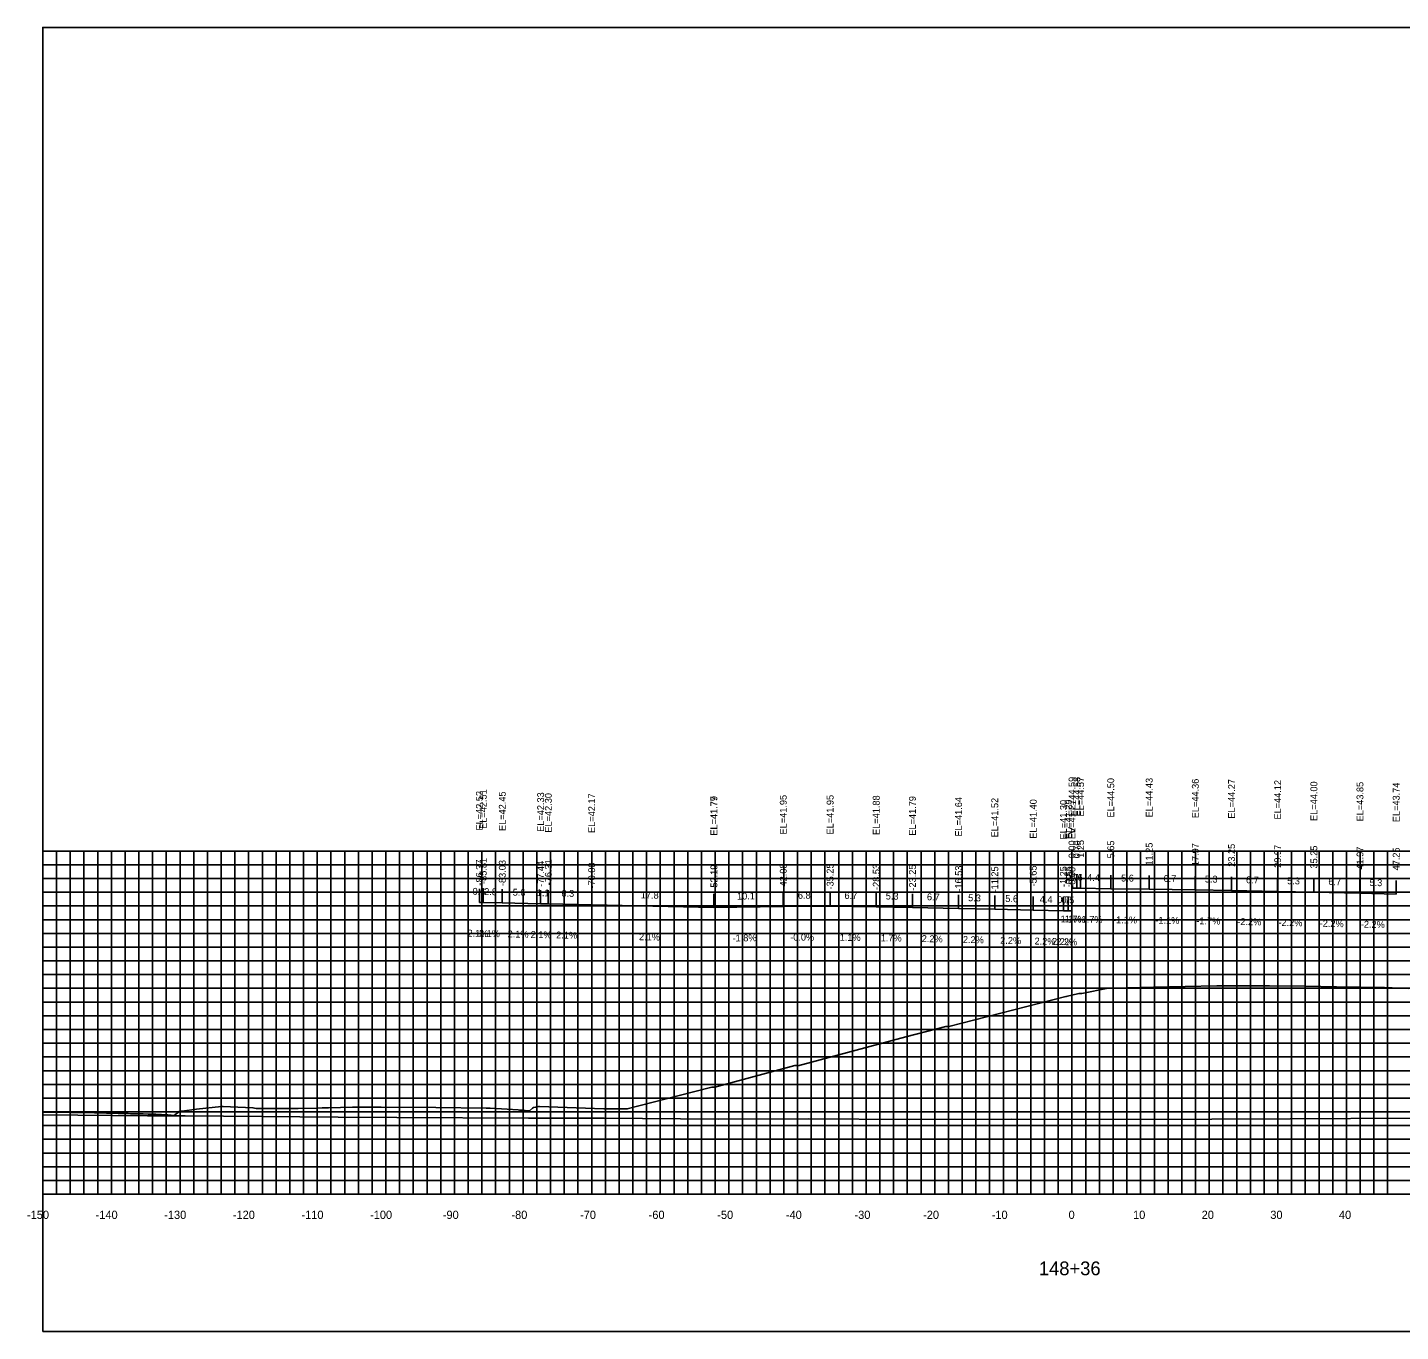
# Model space of a CAD drawing. Extents: x 1800880 to 1818864, y 245271 to 250560.
# Drawn here: x 1809045 to 1809245.1, y 248863.9 to 249053.9 of the extents above; entities that cross this region are included whole.
import ezdxf

# ---------------------------------------------------------------- set-up
doc = ezdxf.new("R2010")
doc.units = 0
for name, color, linetype in [('ANNO-TXT', 7, 'Continuous'), ('AXIS', 7, 'Continuous'), ('CL-CNST', 7, 'Continuous'), ('DESIGN - DRAINAGE - Bridges', 7, 'Continuous'), ('Level 32', 7, 'Continuous'), ('Level 37', 7, 'Continuous'), ('Level 46', 7, 'Continuous'), ('Level 62', 7, 'Continuous'), ('SHT-BDR', 7, 'Continuous')]:
    doc.layers.add(name, color=color, linetype=linetype)

msp = doc.modelspace()

# ---------------------------------------------------------------- linework, layer by layer
at = {"layer": 'AXIS'}
msp.add_lwpolyline([(1809197.26, 248928.49), (1809197.96, 248928.49), (1809198.51, 248928.48), (1809202.91, 248928.4), (1809208.51, 248928.34), (1809215.23, 248928.26), (1809220.51, 248928.17), (1809227.23, 248928.02), (1809232.51, 248927.91), (1809239.23, 248927.76), (1809244.51, 248927.64)], dxfattribs=at)
at = {"layer": 'CL-CNST'}
msp.add_lwpolyline([(1809047.26, 248895.85), (1809047.72, 248895.85), (1809054.78, 248895.76), (1809058.25, 248895.68), (1809058.4, 248895.67), (1809058.57, 248895.67), (1809058.76, 248895.67), (1809058.96, 248895.66), (1809059.19, 248895.66), (1809059.44, 248895.65), (1809059.72, 248895.65), (1809060.04, 248895.64), (1809060.41, 248895.63), (1809060.84, 248895.62), (1809061.33, 248895.61), (1809061.91, 248895.6), (1809062.61, 248895.58), (1809063.47, 248895.56), (1809063.7, 248895.56), (1809063.84, 248895.55), (1809064.27, 248895.53), (1809064.57, 248895.51), (1809064.81, 248895.5), (1809064.99, 248895.49), (1809065.13, 248895.48), (1809065.25, 248895.47), (1809065.35, 248895.47), (1809065.43, 248895.46), (1809065.5, 248895.46), (1809066.44, 248895.4), (1809066.53, 248895.49), (1809067.04, 248895.88), (1809067.05, 248895.92), (1809067.25, 248896), (1809067.57, 248896), (1809069.65, 248896.31), (1809073.31, 248896.71), (1809073.53, 248896.71), (1809074.64, 248896.63), (1809077.89, 248896.51), (1809078.37, 248896.41), (1809078.39, 248896.37), (1809078.39, 248896.37), (1809078.4, 248896.38), (1809078.41, 248896.4), (1809078.41, 248896.4), (1809081.01, 248896.39), (1809082.08, 248896.38), (1809082.45, 248896.38), (1809084.39, 248896.39), (1809084.47, 248896.39), (1809087.23, 248896.45), (1809088, 248896.48), (1809088.9, 248896.5), (1809092.39, 248896.59), (1809096.57, 248896.58), (1809104.53, 248896.55), (1809111.86, 248896.45), (1809111.91, 248896.45), (1809111.92, 248896.45), (1809111.93, 248896.45), (1809111.96, 248896.45), (1809111.96, 248896.44), (1809112.04, 248896.45), (1809112.4, 248896.45), (1809112.45, 248896.45), (1809114.95, 248896.3), (1809116.54, 248896.2), (1809116.56, 248896.2), (1809116.75, 248896.18), (1809116.89, 248896.17), (1809117.01, 248896.16), (1809117.12, 248896.15), (1809117.2, 248896.14), (1809117.27, 248896.14), (1809117.34, 248896.13), (1809117.39, 248896.12), (1809117.44, 248896.12), (1809117.49, 248896.12), (1809117.52, 248896.11), (1809117.56, 248896.11), (1809118.19, 248896.07), (1809118.65, 248896.43), (1809118.8, 248896.54), (1809119.11, 248896.61), (1809119.2, 248896.64), (1809119.23, 248896.65), (1809119.5, 248896.68), (1809119.64, 248896.68), (1809129.04, 248896.34), (1809131.94, 248896.35), (1809132.07, 248896.35), (1809132.44, 248896.35), (1809139.81, 248898.23), (1809144.77, 248899.51), (1809145.19, 248899.52), (1809156.86, 248902.65), (1809157.12, 248902.65), (1809157.32, 248902.64), (1809173.03, 248906.85), (1809178.87, 248908.34), (1809178.96, 248908.36), (1809179.31, 248908.35), (1809196.35, 248912.71), (1809196.42, 248912.71), (1809198.24, 248913.14), (1809198.68, 248913.14), (1809202.54, 248913.93), (1809202.59, 248913.94), (1809202.96, 248913.94), (1809203.03, 248913.94), (1809203.03, 248913.94), (1809203.14, 248913.94), (1809209.12, 248914.08), (1809218.39, 248914.26), (1809220.39, 248914.29), (1809226.04, 248914.25), (1809231.25, 248914.21), (1809235.79, 248914.14), (1809242.81, 248914.04), (1809245.09, 248913.94), (1809246.31, 248913.88)], dxfattribs=at)
at = {"layer": 'DESIGN - DRAINAGE - Bridges'}
for p, q in [((1809047.2, 248933.91), (1809047.26, 248933.91)), ((1809047.26, 248883.91), (1809047.26, 248933.91)), ((1809047.2, 248923.91), (1809047.26, 248923.91)), ((1809047.2, 248913.91), (1809047.26, 248913.91)), ((1809047.2, 248903.91), (1809047.26, 248903.91)), ((1809047.2, 248893.91), (1809047.26, 248893.91)), ((1809047.2, 248883.91), (1809047.26, 248883.91)), ((1809047.26, 248883.91), (1809347.26, 248883.91)), ((1809047.26, 248883.85), (1809047.26, 248883.91)), ((1809057.26, 248883.85), (1809057.26, 248883.91)), ((1809067.26, 248883.85), (1809067.26, 248883.91)), ((1809077.26, 248883.85), (1809077.26, 248883.91)), ((1809087.26, 248883.85), (1809087.26, 248883.91)), ((1809097.26, 248883.85), (1809097.26, 248883.91)), ((1809107.26, 248883.85), (1809107.26, 248883.91)), ((1809117.26, 248883.85), (1809117.26, 248883.91)), ((1809127.26, 248883.85), (1809127.26, 248883.91)), ((1809137.26, 248883.85), (1809137.26, 248883.91)), ((1809147.26, 248883.85), (1809147.26, 248883.91)), ((1809157.26, 248883.85), (1809157.26, 248883.91)), ((1809167.26, 248883.85), (1809167.26, 248883.91)), ((1809177.26, 248883.85), (1809177.26, 248883.91)), ((1809187.26, 248883.85), (1809187.26, 248883.91)), ((1809197.26, 248883.85), (1809197.26, 248883.91)), ((1809207.26, 248883.85), (1809207.26, 248883.91)), ((1809217.26, 248883.85), (1809217.26, 248883.91)), ((1809227.26, 248883.85), (1809227.26, 248883.91)), ((1809237.26, 248883.85), (1809237.26, 248883.91))]:
    msp.add_line(p, q, dxfattribs=at)
at = {"layer": 'Level 37'}
for p, q in [((1809197.26, 248928.49), (1809197.26, 248930.49)), ((1809197.96, 248928.49), (1809197.96, 248930.49)), ((1809198.51, 248928.48), (1809198.51, 248930.48)), ((1809202.91, 248928.4), (1809202.91, 248930.4)), ((1809208.51, 248928.34), (1809208.51, 248930.34)), ((1809215.23, 248928.26), (1809215.23, 248930.26)), ((1809220.51, 248928.17), (1809220.51, 248930.17)), ((1809227.23, 248928.02), (1809227.23, 248930.02)), ((1809232.51, 248927.91), (1809232.51, 248929.91)), ((1809239.23, 248927.76), (1809239.23, 248929.76)), ((1809110.89, 248926.42), (1809110.89, 248928.42)), ((1809111.45, 248926.41), (1809111.45, 248928.41)), ((1809114.23, 248926.35), (1809114.23, 248928.35)), ((1809119.82, 248926.23), (1809119.82, 248928.23)), ((1809120.94, 248926.21), (1809120.94, 248928.21)), ((1809127.26, 248926.08), (1809127.26, 248928.08)), ((1809155.18, 248925.85), (1809155.18, 248927.85)), ((1809162.01, 248925.86), (1809162.01, 248927.86)), ((1809168.73, 248925.78), (1809168.73, 248927.78)), ((1809244.51, 248927.64), (1809244.51, 248929.64)), ((1809145.07, 248925.7), (1809145.07, 248927.7)), ((1809145.07, 248925.67), (1809145.07, 248927.67)), ((1809174.01, 248925.69), (1809174.01, 248927.69)), ((1809180.73, 248925.54), (1809180.73, 248927.54)), ((1809186.01, 248925.43), (1809186.01, 248927.43)), ((1809191.61, 248925.3), (1809191.61, 248927.3)), ((1809196.01, 248925.21), (1809196.01, 248927.21)), ((1809196.71, 248925.19), (1809196.71, 248927.19)), ((1809197.26, 248925.18), (1809197.26, 248927.18))]:
    msp.add_line(p, q, dxfattribs=at)
msp.add_lwpolyline([(1809047.26, 248863.91), (1809347.26, 248863.91), (1809347.26, 249053.91), (1809047.26, 249053.91)], close=True, dxfattribs=at)
at = {"layer": 'Level 46'}
for p, q in [((1809047.26, 248933.91), (1809347.26, 248933.91)), ((1809047.26, 248883.91), (1809047.26, 248933.91)), ((1809049.26, 248883.91), (1809049.26, 248933.91)), ((1809051.26, 248883.91), (1809051.26, 248933.91)), ((1809053.26, 248883.91), (1809053.26, 248933.91)), ((1809055.26, 248883.91), (1809055.26, 248933.91)), ((1809057.26, 248883.91), (1809057.26, 248933.91)), ((1809059.26, 248883.91), (1809059.26, 248933.91)), ((1809061.26, 248883.91), (1809061.26, 248933.91)), ((1809063.26, 248883.91), (1809063.26, 248933.91)), ((1809065.26, 248883.91), (1809065.26, 248933.91)), ((1809067.26, 248883.91), (1809067.26, 248933.91)), ((1809069.26, 248883.91), (1809069.26, 248933.91)), ((1809071.26, 248883.91), (1809071.26, 248933.91)), ((1809073.26, 248883.91), (1809073.26, 248933.91)), ((1809075.26, 248883.91), (1809075.26, 248933.91)), ((1809077.26, 248883.91), (1809077.26, 248933.91)), ((1809079.26, 248883.91), (1809079.26, 248933.91)), ((1809081.26, 248883.91), (1809081.26, 248933.91)), ((1809083.26, 248883.91), (1809083.26, 248933.91)), ((1809085.26, 248883.91), (1809085.26, 248933.91)), ((1809087.26, 248883.91), (1809087.26, 248933.91)), ((1809089.26, 248883.91), (1809089.26, 248933.91)), ((1809091.26, 248883.91), (1809091.26, 248933.91)), ((1809093.26, 248883.91), (1809093.26, 248933.91)), ((1809095.26, 248883.91), (1809095.26, 248933.91)), ((1809097.26, 248883.91), (1809097.26, 248933.91)), ((1809099.26, 248883.91), (1809099.26, 248933.91)), ((1809101.26, 248883.91), (1809101.26, 248933.91)), ((1809103.26, 248883.91), (1809103.26, 248933.91)), ((1809105.26, 248883.91), (1809105.26, 248933.91)), ((1809107.26, 248883.91), (1809107.26, 248933.91)), ((1809109.26, 248883.91), (1809109.26, 248933.91)), ((1809111.26, 248883.91), (1809111.26, 248933.91)), ((1809113.26, 248883.91), (1809113.26, 248933.91)), ((1809115.26, 248883.91), (1809115.26, 248933.91)), ((1809117.26, 248883.91), (1809117.26, 248933.91)), ((1809119.26, 248883.91), (1809119.26, 248933.91)), ((1809121.26, 248883.91), (1809121.26, 248933.91)), ((1809123.26, 248883.91), (1809123.26, 248933.91)), ((1809125.26, 248883.91), (1809125.26, 248933.91)), ((1809127.26, 248883.91), (1809127.26, 248933.91)), ((1809129.26, 248883.91), (1809129.26, 248933.91)), ((1809131.26, 248883.91), (1809131.26, 248933.91)), ((1809133.26, 248883.91), (1809133.26, 248933.91)), ((1809135.26, 248883.91), (1809135.26, 248933.91)), ((1809137.26, 248883.91), (1809137.26, 248933.91)), ((1809139.26, 248883.91), (1809139.26, 248933.91)), ((1809141.26, 248883.91), (1809141.26, 248933.91)), ((1809143.26, 248883.91), (1809143.26, 248933.91)), ((1809145.26, 248883.91), (1809145.26, 248933.91)), ((1809147.26, 248883.91), (1809147.26, 248933.91)), ((1809149.26, 248883.91), (1809149.26, 248933.91)), ((1809151.26, 248883.91), (1809151.26, 248933.91)), ((1809153.26, 248883.91), (1809153.26, 248933.91)), ((1809155.26, 248883.91), (1809155.26, 248933.91)), ((1809157.26, 248883.91), (1809157.26, 248933.91)), ((1809159.26, 248883.91), (1809159.26, 248933.91)), ((1809161.26, 248883.91), (1809161.26, 248933.91)), ((1809163.26, 248883.91), (1809163.26, 248933.91)), ((1809165.26, 248883.91), (1809165.26, 248933.91)), ((1809167.26, 248883.91), (1809167.26, 248933.91)), ((1809169.26, 248883.91), (1809169.26, 248933.91)), ((1809171.26, 248883.91), (1809171.26, 248933.91)), ((1809173.26, 248883.91), (1809173.26, 248933.91)), ((1809175.26, 248883.91), (1809175.26, 248933.91)), ((1809177.26, 248883.91), (1809177.26, 248933.91)), ((1809179.26, 248883.91), (1809179.26, 248933.91)), ((1809181.26, 248883.91), (1809181.26, 248933.91)), ((1809183.26, 248883.91), (1809183.26, 248933.91)), ((1809185.26, 248883.91), (1809185.26, 248933.91)), ((1809187.26, 248883.91), (1809187.26, 248933.91)), ((1809189.26, 248883.91), (1809189.26, 248933.91)), ((1809191.26, 248883.91), (1809191.26, 248933.91)), ((1809193.26, 248883.91), (1809193.26, 248933.91)), ((1809195.26, 248883.91), (1809195.26, 248933.91)), ((1809197.26, 248883.91), (1809197.26, 248933.91)), ((1809199.26, 248883.91), (1809199.26, 248933.91)), ((1809201.26, 248883.91), (1809201.26, 248933.91)), ((1809203.26, 248883.91), (1809203.26, 248933.91)), ((1809205.26, 248883.91), (1809205.26, 248933.91)), ((1809207.26, 248883.91), (1809207.26, 248933.91)), ((1809209.26, 248883.91), (1809209.26, 248933.91)), ((1809211.26, 248883.91), (1809211.26, 248933.91)), ((1809213.26, 248883.91), (1809213.26, 248933.91)), ((1809215.26, 248883.91), (1809215.26, 248933.91)), ((1809217.26, 248883.91), (1809217.26, 248933.91)), ((1809219.26, 248883.91), (1809219.26, 248933.91)), ((1809221.26, 248883.91), (1809221.26, 248933.91)), ((1809223.26, 248883.91), (1809223.26, 248933.91)), ((1809225.26, 248883.91), (1809225.26, 248933.91)), ((1809227.26, 248883.91), (1809227.26, 248933.91)), ((1809229.26, 248883.91), (1809229.26, 248933.91)), ((1809231.26, 248883.91), (1809231.26, 248933.91)), ((1809233.26, 248883.91), (1809233.26, 248933.91)), ((1809235.26, 248883.91), (1809235.26, 248933.91)), ((1809237.26, 248883.91), (1809237.26, 248933.91)), ((1809239.26, 248883.91), (1809239.26, 248933.91)), ((1809241.26, 248883.91), (1809241.26, 248933.91)), ((1809243.26, 248883.91), (1809243.26, 248933.91)), ((1809047.26, 248931.91), (1809347.26, 248931.91)), ((1809047.26, 248929.91), (1809347.26, 248929.91)), ((1809047.26, 248927.91), (1809347.26, 248927.91)), ((1809047.26, 248925.91), (1809347.26, 248925.91)), ((1809047.26, 248923.91), (1809347.26, 248923.91)), ((1809047.26, 248921.91), (1809347.26, 248921.91)), ((1809047.26, 248919.91), (1809347.26, 248919.91)), ((1809047.26, 248917.91), (1809347.26, 248917.91)), ((1809047.26, 248915.91), (1809347.26, 248915.91)), ((1809047.26, 248913.91), (1809347.26, 248913.91)), ((1809047.26, 248911.91), (1809347.26, 248911.91)), ((1809047.26, 248909.91), (1809347.26, 248909.91)), ((1809047.26, 248907.91), (1809347.26, 248907.91)), ((1809047.26, 248905.91), (1809347.26, 248905.91)), ((1809047.26, 248903.91), (1809347.26, 248903.91)), ((1809047.26, 248901.91), (1809347.26, 248901.91)), ((1809047.26, 248899.91), (1809347.26, 248899.91)), ((1809047.26, 248897.91), (1809347.26, 248897.91)), ((1809047.26, 248895.91), (1809347.26, 248895.91)), ((1809047.26, 248893.91), (1809347.26, 248893.91)), ((1809047.26, 248891.91), (1809347.26, 248891.91)), ((1809047.26, 248889.91), (1809347.26, 248889.91)), ((1809047.26, 248887.91), (1809347.26, 248887.91)), ((1809047.26, 248885.91), (1809347.26, 248885.91)), ((1809047.26, 248883.91), (1809347.26, 248883.91))]:
    msp.add_line(p, q, dxfattribs=at)
at = {"layer": 'Level 62'}
for points in [[(1809110.89, 248926.42), (1809111.45, 248926.41), (1809114.23, 248926.35), (1809119.82, 248926.23), (1809120.94, 248926.21), (1809127.26, 248926.08), (1809145.07, 248925.7)], [(1809145.07, 248925.67), (1809155.18, 248925.85), (1809162.01, 248925.86), (1809168.73, 248925.78), (1809174.01, 248925.69), (1809180.73, 248925.54), (1809186.01, 248925.43), (1809191.61, 248925.3), (1809196.01, 248925.21), (1809196.71, 248925.19), (1809197.26, 248925.18)], [(1809047.26, 248895.46), (1809062.53, 248895.35), (1809068.01, 248895.33), (1809090.29, 248895.12), (1809098.84, 248895.11), (1809118.04, 248894.98), (1809129.09, 248894.98), (1809145.8, 248894.86), (1809158.91, 248894.88), (1809173.55, 248894.78), (1809188.4, 248894.83), (1809201.31, 248894.79), (1809217.64, 248894.87), (1809229.07, 248894.88), (1809246.67, 248894.98), (1809256.82, 248894.8), (1809275.54, 248894.91), (1809284.58, 248895.01), (1809292.91, 248894.95), (1809312.33, 248895.07), (1809320.36, 248895.21), (1809340.09, 248895.32), (1809347.26, 248895.13)]]:
    msp.add_lwpolyline(points, dxfattribs=at)

# ---------------------------------------------------------------- texts
for s, p in [('-150', (1809044.96, 248880.31)), ('-140', (1809054.96, 248880.31)), ('-130', (1809064.96, 248880.31)), ('-120', (1809074.96, 248880.31)), ('-110', (1809084.96, 248880.31)), ('-100', (1809094.96, 248880.31)), ('-90', (1809105.56, 248880.31)), ('-80', (1809115.56, 248880.31)), ('-70', (1809125.56, 248880.31)), ('-60', (1809135.56, 248880.31)), ('-50', (1809145.56, 248880.31)), ('-40', (1809155.56, 248880.31)), ('-30', (1809165.56, 248880.31)), ('-20', (1809175.56, 248880.31)), ('-10', (1809185.56, 248880.31)), ('0', (1809196.76, 248880.31)), ('10', (1809206.16, 248880.31)), ('20', (1809216.16, 248880.31)), ('30', (1809226.16, 248880.31)), ('40', (1809236.16, 248880.31))]:
    msp.add_text(s, height=1.2).set_placement(p)
at = {"layer": 'ANNO-TXT'}
for s, rotation, p in [('0.7', 359.3576, (1809196.34, 248929.6)), ('0.6', 359.0171, (1809196.95, 248929.6)), ('4.4', 359.0171, (1809199.45, 248929.56)), ('5.6', 359.3576, (1809204.41, 248929.48)), ('6.7', 359.3576, (1809210.6, 248929.41)), ('5.3', 359.0171, (1809216.61, 248929.34)), ('6.7', 358.7397, (1809222.61, 248929.23)), ('5.3', 358.7397, (1809228.61, 248929.09)), ('6.7', 358.7397, (1809234.61, 248928.96)), ('5.3', 358.7397, (1809240.61, 248928.83)), ('0.6', 358.7824, (1809109.89, 248927.55)), ('2.8', 358.7824, (1809111.58, 248927.51)), ('5.6', 358.778, (1809115.74, 248927.42)), ('1.1', 358.778, (1809119.25, 248927.35)), ('6.3', 358.778, (1809122.84, 248927.27)), ('17.8', 358.778, (1809134.41, 248927.02)), ('10.1', 1.0364, (1809148.45, 248926.83)), ('6.8', 0.0274, (1809157.31, 248926.96)), ('6.7', 359.3576, (1809164.1, 248926.93)), ('5.3', 359.0171, (1809170.11, 248926.86)), ('6.7', 358.7397, (1809176.11, 248926.75)), ('5.3', 358.7397, (1809182.11, 248926.61)), ('5.6', 358.7397, (1809187.53, 248926.49)), ('4.4', 358.7397, (1809192.55, 248926.38)), ('0.7', 358.7397, (1809195.1, 248926.33)), ('0.5', 358.7397, (1809195.72, 248926.31)), ('-1.1%', 359.3576, (1809195.14, 248923.52)), ('-1.7%', 359.0171, (1809195.74, 248923.52)), ('-1.7%', 359.0171, (1809198.21, 248923.48)), ('-1.1%', 359.3576, (1809203.24, 248923.4)), ('-1.1%', 359.3576, (1809209.4, 248923.33)), ('-1.7%', 359.0171, (1809215.37, 248923.26)), ('-2.2%', 358.7397, (1809221.35, 248923.15)), ('-2.2%', 358.7397, (1809227.35, 248923.02)), ('-2.2%', 358.7397, (1809233.35, 248922.89)), ('-2.2%', 358.7397, (1809239.35, 248922.76)), ('2.1%', 358.7824, (1809109.15, 248921.46)), ('2.1%', 358.7824, (1809110.82, 248921.42)), ('2.1%', 358.778, (1809115, 248921.34)), ('2.1%', 358.778, (1809118.36, 248921.26)), ('2.1%', 358.778, (1809122.08, 248921.19)), ('2.1%', 358.778, (1809134.14, 248920.93)), ('-1.8%', 1.0364, (1809147.8, 248920.72)), ('-0.0%', 0.0274, (1809156.19, 248920.86)), ('1.1%', 359.3576, (1809163.4, 248920.84)), ('1.7%', 359.0171, (1809169.37, 248920.77)), ('2.2%', 358.7397, (1809175.35, 248920.66)), ('2.2%', 358.7397, (1809181.35, 248920.53)), ('2.2%', 358.7397, (1809186.79, 248920.41)), ('2.2%', 358.7397, (1809191.79, 248920.3)), ('2.2%', 358.7397, (1809194.34, 248920.24)), ('2.2%', 358.7397, (1809194.96, 248920.23))]:
    msp.add_text(s, height=1, rotation=rotation, dxfattribs=at).set_placement(p)
at = {"layer": 'DESIGN - DRAINAGE - Bridges'}
for s, height, p in [('>', 1.5, (1809196.65, 248936.16)), ('-', 0.0001, (1809047.26, 248883.91))]:
    msp.add_text(s, height=height, dxfattribs=at).set_placement(p)
at = {"layer": 'Level 32'}
msp.add_text('148+36', height=2, dxfattribs=at).set_placement((1809192.43, 248872.11))
at = {"layer": 'SHT-BDR'}
for s, p in [('EL=44.59', (1809197.76, 248938.97)), ('EL=44.58', (1809198.46, 248938.96)), ('EL=44.57', (1809199.01, 248938.95)), ('EL=44.50', (1809203.41, 248938.79)), ('EL=44.43', (1809209.01, 248938.81)), ('EL=44.36', (1809215.73, 248938.69)), ('EL=44.27', (1809221.01, 248938.64)), ('EL=44.12', (1809227.73, 248938.5)), ('EL=44.00', (1809233.01, 248938.3)), ('EL=43.85', (1809239.73, 248938.23)), ('EL=43.74', (1809245.01, 248938.12)), ('EL=42.52', (1809111.39, 248936.9)), ('EL=42.51', (1809111.95, 248937.14)), ('EL=42.45', (1809114.73, 248936.83)), ('EL=42.33', (1809120.32, 248936.71)), ('EL=42.30', (1809121.44, 248936.6)), ('EL=42.17', (1809127.76, 248936.55)), ('EL=41.79', (1809145.57, 248936.17)), ('EL=41.77', (1809145.57, 248936.14)), ('EL=41.95', (1809155.68, 248936.33)), ('EL=41.95', (1809162.51, 248936.33)), ('EL=41.88', (1809169.23, 248936.26)), ('EL=41.79', (1809174.51, 248936.16)), ('EL=41.64', (1809181.23, 248936.02)), ('EL=41.52', (1809186.51, 248935.9)), ('EL=41.40', (1809192.11, 248935.7)), ('EL=41.30', (1809196.51, 248935.6)), ('EL=41.29', (1809197.21, 248935.67)), ('EL=41.27', (1809197.76, 248935.65)), ('0.00', (1809197.76, 248932.86)), ('0.70', (1809198.46, 248932.85)), ('1.25', (1809199.01, 248932.92)), ('5.65', (1809203.41, 248932.84)), ('11.25', (1809209.01, 248931.79)), ('17.97', (1809215.73, 248931.71)), ('23.25', (1809221.01, 248931.62)), ('29.97', (1809227.73, 248931.47)), ('35.25', (1809233.01, 248931.36)), ('41.97', (1809239.73, 248931.21)), ('47.25', (1809245.01, 248931.09)), ('-86.37', (1809111.39, 248928.88)), ('-85.81', (1809111.95, 248929.12)), ('-83.03', (1809114.73, 248928.81)), ('-77.44', (1809120.32, 248928.69)), ('-76.31', (1809121.44, 248928.92)), ('-70.00', (1809127.76, 248928.45)), ('-52.19', (1809145.57, 248928.15)), ('-52.19', (1809145.57, 248928.13)), ('-42.08', (1809155.68, 248928.31)), ('-35.25', (1809162.51, 248928.31)), ('-28.53', (1809169.23, 248928.24)), ('-23.25', (1809174.51, 248928.15)), ('-16.53', (1809181.23, 248928)), ('-5.65', (1809192.11, 248928.75)), ('-11.25', (1809186.51, 248927.88)), ('-1.25', (1809196.51, 248928.66)), ('-0.55', (1809197.21, 248928.64)), ('-0.00', (1809197.76, 248928.55))]:
    msp.add_text(s, height=1, rotation=90, dxfattribs=at).set_placement(p)

doc.saveas('drawing.dxf')
